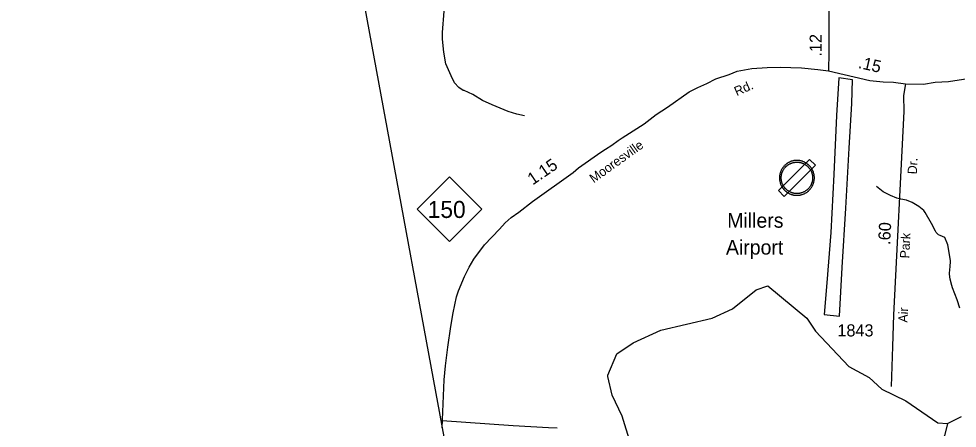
# Model space of a CAD drawing. Extents: x 1473865 to 1648260, y 639067 to 773536.
# Drawn here: x 1473865 to 1483529, y 680616 to 684828 of the extents above; entities that cross this region are included whole.
import ezdxf

# ---------------------------------------------------------------- set-up
doc = ezdxf.new("R2010")
doc.units = 0
for name, color, linetype in [('Exist Aviation Commercial or Municipal Label', 7, 'Continuous'), ('Exist Aviation Commercial or Municipal Perimeter Paved', 7, 'Continuous'), ('Exist Aviation Field Marked Auxiliary CELL', 7, 'Continuous'), ('Exist Boundary Political CountyLine', 7, 'Continuous'), ('Exist Hydrographic Creek Single Shore', 7, 'Continuous'), ('Exist Hydrographic Misc Water Feature', 7, 'Continuous'), ('Exist Road Non-System Type 51', 7, 'Continuous'), ('Exist Road Primary NC Attributed', 7, 'Continuous'), ('Exist Road Primary NC Label', 7, 'Continuous'), ('Exist Road Primary NC Mileage Hundredths English Label', 7, 'Continuous'), ('Exist Road Primary NC Shield CELL', 7, 'Continuous'), ('Exist Road Primary NC Shield Number Label', 7, 'Continuous'), ('Exist Road Secondary Mileage Hundredths English Label', 7, 'Continuous'), ('Exist Road Secondary Type 51 Attributed', 7, 'Continuous'), ('Exist Road Secondary Type 51 Label', 7, 'Continuous'), ('Exist Road Secondary Type 51 Number Label', 7, 'Continuous')]:
    doc.layers.add(name, color=color, linetype=linetype)

msp = doc.modelspace()

# ---------------------------------------------------------------- linework, layer by layer
at = {"layer": 'Exist Aviation Commercial or Municipal Perimeter Paved'}
msp.add_lwpolyline([(1482315.4, 681769.7), (1482345.5, 682269.1), (1482381.4, 682878.7), (1482417.5, 683498.1), (1482443, 683957.6), (1482449.1, 684201.6), (1482309.5, 684221.9), (1482287, 683832.3), (1482257.2, 683226.8), (1482227.5, 682629.3), (1482185, 682111.9), (1482159.6, 681784.2), (1482315.4, 681769.7)], dxfattribs=at)
at = {"layer": 'Exist Aviation Field Marked Auxiliary CELL'}
for points in [[(1482068.9, 683321.9), (1482008.6, 683382.2), (1481687.6, 683061.2), (1481747.9, 683000.9)], [(1481792.6, 683033.6), (1481799.4, 683030.2), (1481802.9, 683028.5), (1481804.8, 683027.7), (1481810.7, 683025.1), (1481811.4, 683024.8), (1481812.9, 683024.3), (1481817.4, 683022.6), (1481820, 683021.6), (1481824.7, 683020.2), (1481828.6, 683018.9), (1481831.2, 683018.2), (1481837.2, 683016.7), (1481838.6, 683016.4), (1481841, 683015.9), (1481844.7, 683015.1), (1481846, 683014.9), (1481847.9, 683014.5), (1481850.2, 683014.2), (1481855.7, 683013.3), (1481860.7, 683012.8), (1481867, 683012.2), (1481872.7, 683012.1), (1481875.9, 683011.9), (1481879.7, 683011.9), (1481884.9, 683011.9), (1481891, 683012.3), (1481898.3, 683013), (1481904.7, 683013.8), (1481910.2, 683014.9), (1481913.1, 683015.3), (1481913.9, 683015.5), (1481915.5, 683015.9), (1481917.7, 683016.4), (1481920.8, 683017.1), (1481922.9, 683017.5), (1481927.6, 683018.8), (1481931.7, 683020.1), (1481933.4, 683020.6), (1481941.8, 683023.5), (1481949.2, 683026.5), (1481953.6, 683028.5), (1481958.9, 683031), (1481964.4, 683033.9), (1481968.5, 683036.1), (1481973.2, 683039), (1481977.7, 683041.9), (1481983, 683045.6), (1481987.7, 683049.2), (1481989.8, 683050.7), (1481990.6, 683051.4), (1481992.5, 683053), (1481995.9, 683055.7), (1482001.1, 683060.5), (1482005.2, 683064.5), (1482008.4, 683067.8), (1482012.1, 683071.6), (1482015.6, 683075.6), (1482018.6, 683079.5), (1482022.8, 683084.7), (1482025.8, 683089), (1482029.1, 683093.9), (1482032, 683098.8), (1482033.4, 683100.9), (1482035.7, 683105.2), (1482038.1, 683109.6), (1482039.6, 683112.7), (1482041.4, 683116.3), (1482043, 683119.9), (1482045.9, 683126.9), (1482046.8, 683129.4), (1482048.4, 683133.9), (1482049.5, 683137.3), (1482050.1, 683139.3), (1482050.9, 683142.1), (1482051.7, 683144.9), (1482052.8, 683149.2), (1482053.7, 683153.2), (1482055.5, 683162.2), (1482055.7, 683163.6), (1482056.3, 683168.6), (1482056.9, 683172.5), (1482057.1, 683175.5), (1482057.7, 683182), (1482057.9, 683189.7), (1482057.9, 683194.8), (1482057.7, 683201.5), (1482057.2, 683207.4), (1482056.9, 683210.3), (1482056.6, 683212.7), (1482056.2, 683215.6), (1482055.6, 683220), (1482055.2, 683222), (1482054.3, 683227.2), (1482054, 683228.8), (1482053.5, 683230.8), (1482052.7, 683234.2), (1482051.7, 683238.1), (1482050.6, 683242.2), (1482049, 683247.5), (1482048.6, 683248.5), (1482047.4, 683252), (1482045.8, 683256.4), (1482043.8, 683261.2), (1482041.8, 683266.2), (1482039.6, 683270.6), (1482036.9, 683275.8), (1482034.7, 683279.8), (1482033.4, 683282.1), (1482032.6, 683283.4), (1482030.5, 683286.8), (1482028.1, 683290.8), (1482025, 683295.2), (1482022.1, 683299.1), (1482018.8, 683303.7), (1482016, 683306.8), (1482012.3, 683311.1), (1482008.9, 683314.9), (1482005.4, 683318.4), (1482004.5, 683319.3), (1482002.6, 683321.2), (1481999.7, 683323.9), (1481995.7, 683327.6), (1481991.8, 683330.7), (1481987.7, 683333.9), (1481984.2, 683336.6), (1481982.7, 683337.7), (1481981.9, 683338.3), (1481980.3, 683339.3), (1481977.4, 683341.3), (1481974.4, 683343.2), (1481971.8, 683344.9), (1481967.7, 683347.3), (1481960.8, 683351.1), (1481957.5, 683352.7), (1481956.6, 683353.2), (1481952.2, 683355.2), (1481947.4, 683357.4), (1481940.8, 683359.9), (1481937.9, 683360.9), (1481934.2, 683362.2), (1481932.5, 683362.8), (1481927.4, 683364.4), (1481922.7, 683365.6), (1481921, 683366), (1481916.8, 683366.9), (1481912.1, 683368), (1481907.6, 683368.7), (1481904.3, 683369.3), (1481896.2, 683370.2), (1481894.8, 683370.4), (1481890.7, 683370.7), (1481886.3, 683371), (1481885.3, 683371), (1481875.4, 683371.3), (1481869.3, 683371), (1481865.5, 683370.7), (1481857.4, 683370), (1481856.8, 683369.9), (1481853.6, 683369.4), (1481850.2, 683368.9), (1481847.6, 683368.6), (1481845.7, 683368.2), (1481840.2, 683367.1), (1481837.4, 683366.5), (1481834.7, 683365.8), (1481829.4, 683364.4), (1481824.4, 683362.8), (1481820.6, 683361.7), (1481819.6, 683361.3), (1481813.2, 683359), (1481810.9, 683358.1), (1481809.6, 683357.5), (1481804.3, 683355.3), (1481800.7, 683353.6), (1481794.4, 683350.6), (1481791, 683348.5), (1481786.1, 683345.7), (1481782.5, 683343.6), (1481778.7, 683341), (1481775.7, 683339), (1481771.5, 683336), (1481769.1, 683334.1), (1481763.5, 683329.7), (1481762.4, 683328.8), (1481759.5, 683326.2), (1481756.6, 683323.7), (1481755.9, 683323.1), (1481753.2, 683320.5), (1481749.3, 683316.6), (1481746.5, 683313.5), (1481743.6, 683310.5), (1481739.7, 683306), (1481735.5, 683300.6), (1481732.1, 683295.9), (1481731.3, 683294.8), (1481730.5, 683293.7), (1481729.1, 683291.5), (1481728.4, 683290.5), (1481726.1, 683287), (1481722.2, 683280.3), (1481721.9, 683279.8), (1481720.9, 683278.1), (1481719.9, 683276.3), (1481717.1, 683270.9), (1481715.9, 683268.3), (1481712.5, 683260.8), (1481709.1, 683251.9), (1481707.6, 683247.4), (1481706.1, 683242.6), (1481705.7, 683241.2), (1481705, 683238.7), (1481703.9, 683234.6), (1481703.6, 683233.4), (1481702.2, 683226.9), (1481701.6, 683224.2), (1481701.3, 683222.1), (1481700.6, 683217.5), (1481700.3, 683216), (1481700.1, 683214.5), (1481699.7, 683210.8), (1481699.3, 683206.2), (1481699.1, 683204.3), (1481699, 683202.5), (1481698.8, 683197.8), (1481698.7, 683195.6), (1481698.7, 683191.6), (1481698.7, 683188.3), (1481698.8, 683183.2), (1481699.1, 683178.9), (1481699.2, 683177.5), (1481699.6, 683173.5), (1481700.2, 683168.4), (1481700.5, 683166), (1481700.8, 683164), (1481701.7, 683158.4), (1481702.9, 683152.7), (1481704.2, 683147.1), (1481705.7, 683141.5), (1481707, 683137.5), (1481708.6, 683132.5), (1481709.2, 683130.9), (1481710.8, 683126.8), (1481713.3, 683120.5), (1481716.2, 683114), (1481718.8, 683108.9), (1481719.8, 683107), (1481720.8, 683105.1), (1481722.8, 683101.7), (1481723.3, 683100.8), (1481725.8, 683096.6), (1481728.5, 683092.4), (1481730.9, 683088.8), (1481731.4, 683088.1), (1481734.2, 683084.4), (1481735.1, 683083.2), (1481736.4, 683081.3), (1481737.6, 683079.9), (1481738.8, 683078.5), (1481740.3, 683076.6), (1481741.7, 683074.9), (1481742.5, 683074), (1481744.3, 683072), (1481747.2, 683068.7), (1481748.5, 683067.3), (1481751.3, 683064.6), (1481753.8, 683062.1), (1481755.5, 683060.4), (1481757.5, 683058.7), (1481761.1, 683055.5), (1481762.6, 683054.1), (1481767, 683050.6), (1481769.2, 683048.9), (1481770.3, 683048), (1481775, 683044.6), (1481779.5, 683041.7), (1481785.7, 683037.7)], [(1481801.1, 683049.2), (1481794.9, 683053), (1481789.3, 683056.5), (1481785.3, 683059.2), (1481781, 683062.2), (1481780, 683063), (1481778, 683064.6), (1481774.1, 683067.8), (1481772.7, 683068.9), (1481769.5, 683071.8), (1481767.7, 683073.4), (1481766.1, 683074.9), (1481763.9, 683077.1), (1481761.4, 683079.6), (1481760.2, 683080.9), (1481757.6, 683083.8), (1481755.9, 683085.6), (1481755.2, 683086.5), (1481753.9, 683088), (1481752.6, 683089.7), (1481751.5, 683091), (1481750.5, 683092.2), (1481749.2, 683093.9), (1481748.5, 683095), (1481746, 683098.3), (1481745.5, 683099), (1481743.4, 683102.2), (1481740.9, 683106), (1481738.7, 683109.8), (1481738.2, 683110.6), (1481736.4, 683113.7), (1481735.5, 683115.4), (1481734.6, 683117.1), (1481732.3, 683121.7), (1481729.6, 683127.5), (1481727.4, 683133.2), (1481725.9, 683136.9), (1481725.5, 683138.3), (1481724, 683142.8), (1481722.8, 683146.4), (1481721.5, 683151.5), (1481720.3, 683156.5), (1481719.2, 683161.7), (1481718.4, 683166.8), (1481718.1, 683168.6), (1481717.8, 683170.7), (1481717.3, 683175.3), (1481716.9, 683178.9), (1481716.9, 683180.1), (1481716.6, 683184), (1481716.5, 683188.6), (1481716.5, 683191.6), (1481716.5, 683195.2), (1481716.6, 683197.2), (1481716.8, 683201.4), (1481716.9, 683203.1), (1481717, 683204.8), (1481717.4, 683208.9), (1481717.8, 683212.2), (1481718, 683213.6), (1481718.2, 683214.9), (1481718.9, 683219.1), (1481719.1, 683220.9), (1481719.6, 683223.4), (1481720.9, 683229.3), (1481721.2, 683230.3), (1481722.2, 683234), (1481722.8, 683236.3), (1481723.1, 683237.6), (1481724.5, 683241.9), (1481725.9, 683245.9), (1481729, 683254), (1481732, 683260.7), (1481733.1, 683263), (1481735.6, 683267.9), (1481736.5, 683269.5), (1481737.4, 683271.1), (1481737.7, 683271.5), (1481741.1, 683277.5), (1481743.3, 683280.7), (1481743.9, 683281.6), (1481745.2, 683283.6), (1481745.9, 683284.6), (1481746.6, 683285.5), (1481749.6, 683289.8), (1481753.4, 683294.7), (1481756.9, 683298.7), (1481759.6, 683301.4), (1481762, 683304.2), (1481765.6, 683307.7), (1481768.1, 683310), (1481768.7, 683310.6), (1481771.2, 683312.9), (1481773.9, 683315.2), (1481774.8, 683316), (1481779.9, 683320), (1481782.1, 683321.7), (1481785.8, 683324.4), (1481788.5, 683326.2), (1481792, 683328.5), (1481795.3, 683330.5), (1481799.7, 683333), (1481802.7, 683334.9), (1481808.4, 683337.5), (1481811.6, 683339), (1481816.4, 683341), (1481817.6, 683341.6), (1481819.6, 683342.4), (1481825.4, 683344.5), (1481826.3, 683344.8), (1481829.8, 683345.9), (1481834.2, 683347.3), (1481839, 683348.5), (1481841.5, 683349.1), (1481844, 683349.7), (1481848.9, 683350.7), (1481850.7, 683351), (1481852.9, 683351.3), (1481856.1, 683351.8), (1481858.9, 683352.2), (1481859.5, 683352.3), (1481866.8, 683353), (1481870.2, 683353.2), (1481875.7, 683353.5), (1481884.6, 683353.2), (1481885.5, 683353.2), (1481889.5, 683353), (1481893.2, 683352.7), (1481894.4, 683352.5), (1481901.7, 683351.7), (1481904.7, 683351.2), (1481908.8, 683350.5), (1481912.9, 683349.6), (1481916.8, 683348.7), (1481918.3, 683348.3), (1481922.5, 683347.2), (1481927.1, 683345.8), (1481928.6, 683345.3), (1481932, 683344.1), (1481934.6, 683343.2), (1481940.6, 683341), (1481944.9, 683339), (1481948.8, 683337.1), (1481949.6, 683336.8), (1481952.6, 683335.3), (1481958.8, 683331.9), (1481962.5, 683329.7), (1481964.9, 683328.2), (1481967.6, 683326.5), (1481970.2, 683324.7), (1481971.6, 683323.7), (1481972.4, 683323.2), (1481973.7, 683322.2), (1481976.9, 683319.8), (1481980.5, 683316.9), (1481984, 683314.1), (1481987.6, 683310.8), (1481990.3, 683308.3), (1481992, 683306.7), (1481992.8, 683305.8), (1481995.9, 683302.7), (1481999.1, 683299.3), (1482002.4, 683295.4), (1482004.8, 683292.6), (1482007.8, 683288.5), (1482010.5, 683284.9), (1482013.2, 683281), (1482015.5, 683277.3), (1482017.3, 683274.3), (1482018, 683273.1), (1482019.2, 683271), (1482021.2, 683267.5), (1482023.6, 683262.8), (1482025.6, 683258.8), (1482027.4, 683254.3), (1482029.2, 683250), (1482030.6, 683246), (1482031.7, 683242.9), (1482032.1, 683241.9), (1482033.5, 683237.2), (1482034.5, 683233.5), (1482035.4, 683230), (1482036.2, 683226.9), (1482036.6, 683225.1), (1482036.8, 683223.7), (1482037.7, 683219), (1482038.1, 683217.2), (1482038.6, 683213.3), (1482038.9, 683210.6), (1482039.2, 683208.4), (1482039.5, 683205.9), (1482039.9, 683200.5), (1482040.1, 683194.5), (1482040.1, 683189.9), (1482039.9, 683182.9), (1482039.4, 683177.1), (1482039.2, 683174.4), (1482038.7, 683170.8), (1482038.1, 683166.4), (1482037.9, 683165.1), (1482036.4, 683157), (1482035.5, 683153.4), (1482034.5, 683149.6), (1482033.8, 683147), (1482033, 683144.5), (1482032.5, 683142.7), (1482031.6, 683139.6), (1482030.1, 683135.6), (1482029.2, 683133.3), (1482026.6, 683127), (1482025.2, 683123.8), (1482023.6, 683120.5), (1482022.3, 683117.7), (1482020.1, 683113.8), (1482018, 683109.9), (1482016.8, 683108), (1482014.1, 683103.6), (1482011.2, 683099.1), (1482008.5, 683095.3), (1482004.7, 683090.6), (1482002, 683087.1), (1481998.8, 683083.5), (1481995.5, 683080), (1481992.6, 683077.1), (1481988.9, 683073.5), (1481984.2, 683069.2), (1481981.2, 683066.7), (1481979.5, 683065.3), (1481978.7, 683064.7), (1481976.9, 683063.3), (1481972.6, 683060.1), (1481967.9, 683056.7), (1481963.8, 683054.1), (1481959.6, 683051.5), (1481955.9, 683049.5), (1481951, 683046.9), (1481946.1, 683044.7), (1481942.2, 683042.8), (1481935.5, 683040.2), (1481927.9, 683037.5), (1481926.4, 683037.1), (1481922.7, 683035.9), (1481918.5, 683034.8), (1481916.6, 683034.4), (1481913.8, 683033.7), (1481911.8, 683033.3), (1481910.4, 683032.9), (1481909.6, 683032.8), (1481907, 683032.4), (1481902, 683031.4), (1481896.3, 683030.7), (1481889.7, 683030.1), (1481884.2, 683029.7), (1481879.5, 683029.7), (1481876.1, 683029.7), (1481873.3, 683029.8), (1481868.1, 683030), (1481862.5, 683030.5), (1481857.9, 683031), (1481853, 683031.8), (1481850.9, 683032), (1481849.2, 683032.4), (1481848.1, 683032.6), (1481844.7, 683033.3), (1481842.5, 683033.7), (1481841.2, 683034), (1481835.9, 683035.4), (1481833.5, 683036), (1481830, 683037.1), (1481825.8, 683038.5), (1481823.4, 683039.3), (1481819.4, 683040.8), (1481818, 683041.3), (1481817.4, 683041.6), (1481812, 683043.9), (1481810.4, 683044.6), (1481807.2, 683046.2)]]:
    msp.add_lwpolyline(points, close=True, dxfattribs=at)
at = {"layer": 'Exist Boundary Political CountyLine'}
msp.add_lwpolyline([(1493929.8, 769716.1), (1473865.2, 704260.4), (1482487.1, 657504)], dxfattribs=at)
at = {"layer": 'Exist Hydrographic Creek Single Shore'}
msp.add_line((1479929.9, 681148.4), (1479930.2, 681161.3), dxfattribs=at)
for points in [[(1479930.2, 681161.3), (1480023.7, 681379.5), (1480191.6, 681494.2), (1480477.7, 681623.1), (1481004.7, 681747), (1481214.6, 681844.6), (1481459.7, 682039.8), (1481577.7, 682080.2), (1481979.7, 681747.1), (1482069.7, 681614), (1482413.7, 681249.2), (1482620.7, 681136.7), (1482751.7, 681015.9), (1482999.7, 680896), (1483329.6, 680672.7), (1483428.7, 680664.1), (1483571.7, 680736.8)], [(1480118.5, 679500.3), (1480309, 679583.2), (1480350.5, 679774), (1480283.6, 680041.5), (1480195.6, 680269.8), (1480165.7, 680460.8), (1480078.7, 680738.3), (1479974.7, 680957.1), (1479929.9, 681148.4)]]:
    msp.add_lwpolyline(points, dxfattribs=at)
at = {"layer": 'Exist Hydrographic Misc Water Feature'}
for points in [[(1479072.9, 683831.5), (1478993.2, 683847.3), (1478905.8, 683873.2), (1478741, 683943.6), (1478640.2, 683986.9), (1478542.3, 684050.4), (1478450.4, 684091), (1478442.4, 684091.1), (1478397.1, 684120.1), (1478352.1, 684169.1), (1478317.7, 684241.8), (1478262.8, 684364), (1478242.8, 684483.4), (1478230.9, 684583.6), (1478227.7, 684623.7), (1478229.1, 684687.6), (1478246.6, 684905.5)], [(1483557.6, 681852.3), (1483527.9, 681935.3), (1483481.2, 682060.7), (1483473.8, 682085.7), (1483454.9, 682150), (1483447.9, 682200.1), (1483452.8, 682254), (1483457.1, 682269.9), (1483458.4, 682341.8), (1483433.3, 682502.2), (1483402.6, 682578.7), (1483354.8, 682598.4), (1483335.2, 682604), (1483313.6, 682628.4), (1483305.9, 682642.5), (1483265.3, 682721.2), (1483199.3, 682834.4), (1483185.7, 682854.6), (1483132.5, 682895.6), (1483065.2, 682936.8), (1483005.7, 682962), (1482949.8, 682971), (1482906.1, 682983.8), (1482840.5, 683009), (1482767.2, 683046.4), (1482696.2, 683101.7)], [(1483428.7, 680664.1), (1483397.8, 680538.1), (1483292.7, 680370.1), (1483228, 680219.5), (1483198.7, 680144.1), (1483187.5, 680076.3), (1483175.4, 679964.6), (1483170.5, 679910.8), (1483168.6, 679804.9), (1483178.2, 679723.8), (1483208.1, 679662.5), (1483323, 679498.2), (1483460.1, 679335.7), (1483527.5, 679256), (1483577.5, 679189.6), (1483597.3, 679123.2), (1483596.1, 679117.2), (1483617.3, 679076.9), (1483644.7, 679040.4), (1483668.3, 679015.9), (1483847.4, 678860.7)]]:
    msp.add_lwpolyline(points, dxfattribs=at)
at = {"layer": 'Exist Road Non-System Type 51'}
msp.add_lwpolyline([(1479409.9, 680617), (1479318.6, 680618.9), (1478955.6, 680639.4), (1478225, 680691.5)], dxfattribs=at)
at = {"layer": 'Exist Road Primary NC Attributed'}
for points in [[(1482997.2, 684157.6), (1483180.1, 684154.7), (1483302.4, 684175.8), (1483440.4, 684183.6), (1483636.9, 684212.3), (1483755.6, 684235.7), (1483900.1, 684266.3), (1484381.6, 684378), (1485306.5, 684568.6), (1485864.5, 684691.2), (1486063.4, 684742)], [(1478224.6, 680619.2), (1478245.5, 681112.6), (1478260.4, 681256), (1478285, 681450.2), (1478312.8, 681663.7), (1478337, 681803.3), (1478373.7, 681968.7), (1478394.7, 682028.3), (1478455.3, 682175.3), (1478504.9, 682272.4), (1478550.2, 682355.7), (1478662.8, 682502.7), (1478815.6, 682665.4), (1478872.7, 682728.5), (1478934.1, 682783), (1479015.9, 682840.3), (1479155.4, 682947.8), (1479574.8, 683245.2), (1479630.5, 683293.9), (1479858.5, 683457.6), (1479906.4, 683488), (1479972, 683529.7), (1480037.6, 683577.7), (1480077.3, 683603.5), (1480304.3, 683747), (1480430.1, 683841.9), (1480546.2, 683919.1), (1480768.5, 684077.3), (1480858.3, 684122.5), (1480951.6, 684163.8), (1481044.5, 684211), (1481179.1, 684254.7), (1481261.3, 684290.4), (1481412.9, 684317.4), (1481573.1, 684328.5), (1481705, 684330.5), (1481925, 684324.9), (1482092.7, 684308.1), (1482202.4, 684292.2)], [(1482202.4, 684292.2), (1482628.7, 684194.8), (1482765.8, 684180.5), (1482874.4, 684174.8), (1482997.2, 684157.6)]]:
    msp.add_lwpolyline(points, dxfattribs=at)
at = {"layer": 'Exist Road Primary NC Shield CELL'}
msp.add_lwpolyline([(1477967.5, 682868.6), (1478300.5, 683201.6), (1478633.5, 682868.6), (1478300.5, 682535.6)], close=True, dxfattribs=at)
at = {"layer": 'Exist Road Secondary Type 51 Attributed'}
for points in [[(1482208.6, 684914.6), (1482205.8, 684486.5), (1482202.4, 684292.2)], [(1482997.2, 684157.6), (1482977.2, 684037.5), (1482980.7, 683873), (1482872.3, 681783.8), (1482863.2, 681454.8), (1482847.4, 681043.4)]]:
    msp.add_lwpolyline(points, dxfattribs=at)

# ---------------------------------------------------------------- texts
at = {"layer": 'Exist Aviation Commercial or Municipal Label'}
for s, p in [('Millers', (1481160.7, 682678.5)), ('Airport', (1481147.3, 682402.2))]:
    msp.add_text(s, height=150, dxfattribs=at).set_placement(p)
at = {"layer": 'Exist Road Primary NC Label'}
for s, rotation, p in [('Rd.', 23.90113, (1481258.5, 684031.9)), ('Mooresville', 35.60715, (1479785.1, 683134.8))]:
    msp.add_text(s, height=95, rotation=rotation, dxfattribs=at).set_placement(p)
at = {"layer": 'Exist Road Primary NC Mileage Hundredths English Label'}
for s, rotation, p in [('.15', 347.12057, (1482503.2, 684323)), ('1.15', 34.2792, (1479157.4, 683112.8))]:
    msp.add_text(s, height=125, rotation=rotation, dxfattribs=at).set_placement(p)
at = {"layer": 'Exist Road Primary NC Shield Number Label'}
msp.add_text('150', height=175, dxfattribs=at).set_placement((1478076.6, 682778.9))
at = {"layer": 'Exist Road Secondary Mileage Hundredths English Label'}
for s, rotation, p in [('.12', 89.62942, (1482133, 684439.1)), ('.60', 87.0211, (1482837.8, 682500.2))]:
    msp.add_text(s, height=125, rotation=rotation, dxfattribs=at).set_placement(p)
at = {"layer": 'Exist Road Secondary Type 51 Label'}
for s, p in [('Dr.', (1483112.1, 683226.6)), ('Park', (1483034, 682361.1)), ('Air', (1483016.5, 681701.1))]:
    msp.add_text(s, height=95, rotation=87.0211, dxfattribs=at).set_placement(p)
at = {"layer": 'Exist Road Secondary Type 51 Number Label'}
msp.add_text('1843', height=125, dxfattribs=at).set_placement((1482295.1, 681559.9))

doc.saveas('drawing.dxf')
